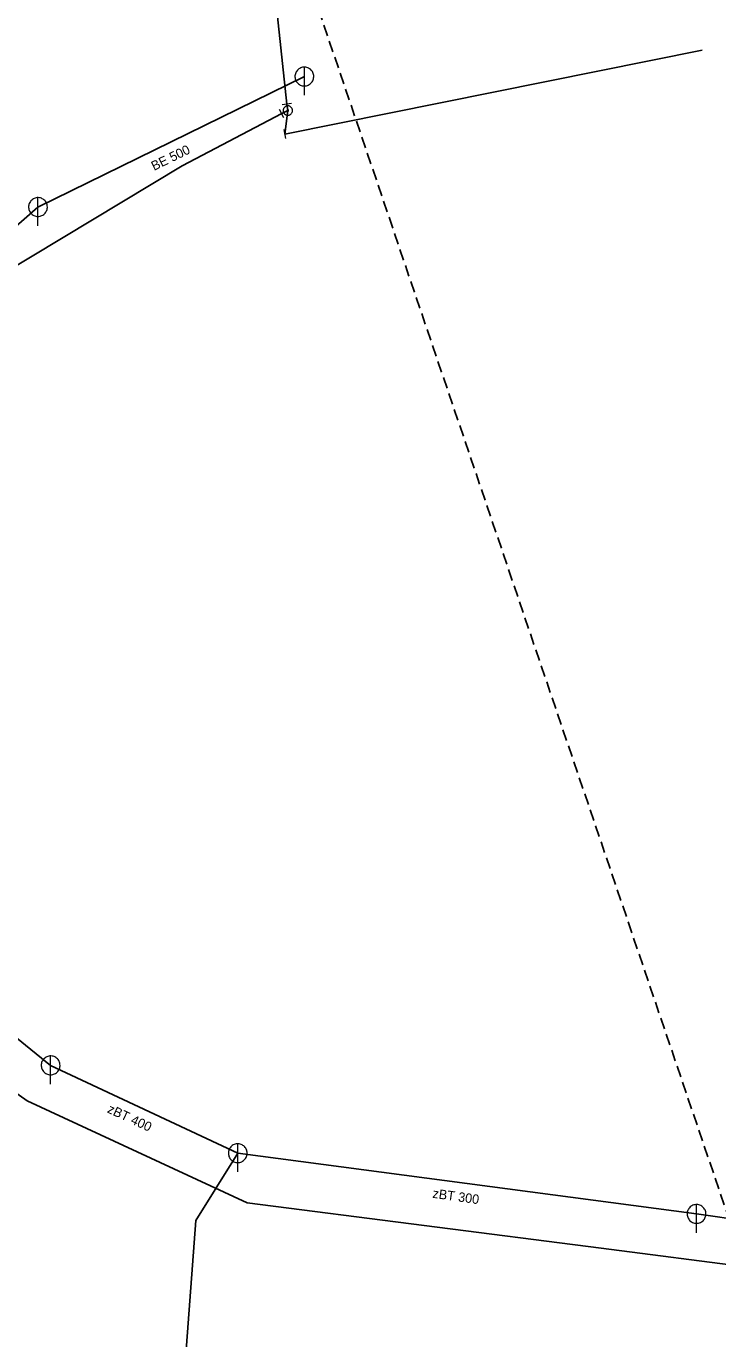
# Model space of a CAD drawing. Extents: x -659250 to -657316, y -997555 to -993684.
# Drawn here: x -658197.6 to -658124, y -995125.1 to -994985.4 of the extents above; entities that cross this region are included whole.
import ezdxf

# ---------------------------------------------------------------- set-up
doc = ezdxf.new("R2010")
doc.units = 0
doc.header["$LTSCALE"] = 0.4
doc.linetypes.add('MEDIUM_DASHED', pattern=[4.5, 3, -1.5])
doc.layers.add('1', color=7, linetype='Continuous')
for name, color, linetype, lineweight in [('14', 7, 'Continuous', 25), ('17', 7, 'Continuous', 25), ('22', 7, 'Continuous', 13), ('34', 7, 'Continuous', 13), ('47', 7, 'Continuous', 13), ('63', 7, 'MEDIUM_DASHED', 25)]:
    doc.layers.add(name, color=color, linetype=linetype, lineweight=lineweight)

msp = doc.modelspace()

# ---------------------------------------------------------------- linework, layer by layer
at = {"layer": '14'}
for p, q in [((-658168, -994990.77), (-658196.329, -995004.66)), ((-658196.329, -995004.66), (-658210.829, -995017.39)), ((-658230.69, -995067.21), (-658194.982, -995096.022)), ((-658194.982, -995096.022), (-658175.079, -995105.37)), ((-658126.289, -995111.84), (-658175.079, -995105.37)), ((-658069.557, -995119.87), (-658126.289, -995111.84))]:
    msp.add_line(p, q, dxfattribs=at)
msp.add_lwpolyline([(-658175.079, -995105.37), (-658179.557, -995112.526), (-658182.53, -995152.469), (-658232.25, -995143.89), (-658272.949, -995138.75)], dxfattribs=at)
at = {"layer": '17'}
for p, q in [((-658170.079, -994996.89), (-658125.679, -994987.972)), ((-658169.756, -994994.391), (-658170.41, -994994.71)), ((-658169.756, -994994.391), (-658170.079, -994996.89)), ((-658169.87, -994993.71), (-658169.756, -994994.391))]:
    msp.add_line(p, q, dxfattribs=at)
for points in [[(-658177.25, -994941.239), (-658174.441, -994950.724), (-658169.87, -994993.71)], [(-658170.41, -994994.71), (-658180.989, -995000.263), (-658235.118, -995032.881), (-658258.852, -995047.041), (-658259.263, -995047.311)], [(-658062.373, -995124.127), (-658085.166, -995121.715), (-658104.599, -995119.601), (-658136.438, -995115.484), (-658174.067, -995110.673), (-658197.491, -995099.798), (-658221.556, -995082.743), (-658257.348, -995050.168), (-658259.263, -995047.311)]]:
    msp.add_lwpolyline(points, dxfattribs=at)
at = {"layer": '22'}
for p, q in [((-658168, -994992.77), (-658167.999, -994989.77)), ((-658196.329, -995006.66), (-658196.328, -995003.66)), ((-658194.982, -995098.022), (-658194.981, -995095.022)), ((-658175.079, -995107.37), (-658175.078, -995104.37)), ((-658126.289, -995113.84), (-658126.288, -995110.84))]:
    msp.add_line(p, q, dxfattribs=at)
for points in [[(-658167, -994990.77), (-658167.005, -994990.661), (-658167.023, -994990.553), (-658167.053, -994990.447), (-658167.093, -994990.346), (-658167.145, -994990.249), (-658167.207, -994990.159), (-658167.279, -994990.076), (-658167.359, -994990.002), (-658167.447, -994989.936), (-658167.541, -994989.881), (-658167.641, -994989.836), (-658167.746, -994989.803), (-658167.853, -994989.781), (-658167.962, -994989.771), (-658168.072, -994989.773), (-658168.18, -994989.787), (-658168.287, -994989.812), (-658168.39, -994989.849), (-658168.488, -994989.898), (-658168.58, -994989.956), (-658168.666, -994990.025), (-658168.743, -994990.102), (-658168.812, -994990.188), (-658168.871, -994990.28), (-658168.919, -994990.378), (-658168.956, -994990.481), (-658168.982, -994990.588), (-658168.996, -994990.696), (-658168.999, -994990.806), (-658168.989, -994990.915), (-658168.968, -994991.022), (-658168.934, -994991.126), (-658168.89, -994991.226), (-658168.835, -994991.321), (-658168.769, -994991.409), (-658168.695, -994991.489), (-658168.612, -994991.561), (-658168.522, -994991.623), (-658168.426, -994991.675), (-658168.324, -994991.716), (-658168.219, -994991.746), (-658168.111, -994991.764), (-658168.001, -994991.77), (-658167.892, -994991.764), (-658167.784, -994991.746), (-658167.679, -994991.717), (-658167.577, -994991.676), (-658167.48, -994991.624), (-658167.39, -994991.562), (-658167.307, -994991.491), (-658167.232, -994991.411), (-658167.167, -994991.323), (-658167.111, -994991.229), (-658167.067, -994991.129), (-658167.033, -994991.025), (-658167.011, -994990.917), (-658167.001, -994990.808)], [(-658195.329, -995004.66), (-658195.334, -995004.551), (-658195.352, -995004.443), (-658195.382, -995004.337), (-658195.422, -995004.236), (-658195.474, -995004.139), (-658195.536, -995004.049), (-658195.608, -995003.966), (-658195.688, -995003.892), (-658195.776, -995003.826), (-658195.87, -995003.771), (-658195.97, -995003.726), (-658196.075, -995003.693), (-658196.182, -995003.671), (-658196.291, -995003.661), (-658196.401, -995003.663), (-658196.509, -995003.677), (-658196.616, -995003.702), (-658196.719, -995003.739), (-658196.817, -995003.788), (-658196.909, -995003.846), (-658196.995, -995003.915), (-658197.072, -995003.992), (-658197.141, -995004.078), (-658197.2, -995004.17), (-658197.248, -995004.268), (-658197.285, -995004.371), (-658197.311, -995004.478), (-658197.325, -995004.586), (-658197.328, -995004.696), (-658197.318, -995004.805), (-658197.297, -995004.912), (-658197.263, -995005.016), (-658197.219, -995005.116), (-658197.164, -995005.211), (-658197.098, -995005.299), (-658197.024, -995005.379), (-658196.941, -995005.451), (-658196.851, -995005.513), (-658196.755, -995005.565), (-658196.653, -995005.606), (-658196.548, -995005.636), (-658196.44, -995005.654), (-658196.33, -995005.66), (-658196.221, -995005.654), (-658196.113, -995005.636), (-658196.008, -995005.607), (-658195.906, -995005.566), (-658195.809, -995005.514), (-658195.719, -995005.452), (-658195.636, -995005.381), (-658195.561, -995005.301), (-658195.496, -995005.213), (-658195.44, -995005.119), (-658195.396, -995005.019), (-658195.362, -995004.915), (-658195.34, -995004.807), (-658195.33, -995004.698)], [(-658193.982, -995096.022), (-658193.987, -995095.913), (-658194.005, -995095.805), (-658194.035, -995095.699), (-658194.075, -995095.598), (-658194.127, -995095.501), (-658194.189, -995095.411), (-658194.261, -995095.328), (-658194.341, -995095.254), (-658194.429, -995095.188), (-658194.523, -995095.133), (-658194.623, -995095.088), (-658194.728, -995095.055), (-658194.835, -995095.033), (-658194.944, -995095.023), (-658195.054, -995095.025), (-658195.162, -995095.039), (-658195.269, -995095.064), (-658195.372, -995095.101), (-658195.47, -995095.15), (-658195.562, -995095.208), (-658195.648, -995095.277), (-658195.725, -995095.354), (-658195.794, -995095.44), (-658195.853, -995095.532), (-658195.901, -995095.63), (-658195.938, -995095.733), (-658195.964, -995095.84), (-658195.978, -995095.948), (-658195.981, -995096.058), (-658195.971, -995096.167), (-658195.95, -995096.274), (-658195.916, -995096.378), (-658195.872, -995096.478), (-658195.817, -995096.573), (-658195.751, -995096.661), (-658195.677, -995096.741), (-658195.594, -995096.813), (-658195.504, -995096.875), (-658195.408, -995096.927), (-658195.306, -995096.968), (-658195.201, -995096.998), (-658195.093, -995097.016), (-658194.983, -995097.022), (-658194.874, -995097.016), (-658194.766, -995096.998), (-658194.661, -995096.969), (-658194.559, -995096.928), (-658194.462, -995096.876), (-658194.372, -995096.814), (-658194.289, -995096.743), (-658194.214, -995096.663), (-658194.149, -995096.575), (-658194.093, -995096.481), (-658194.049, -995096.381), (-658194.015, -995096.277), (-658193.993, -995096.169), (-658193.983, -995096.06)], [(-658174.079, -995105.37), (-658174.084, -995105.261), (-658174.102, -995105.153), (-658174.132, -995105.047), (-658174.172, -995104.946), (-658174.224, -995104.849), (-658174.286, -995104.759), (-658174.358, -995104.676), (-658174.438, -995104.602), (-658174.526, -995104.536), (-658174.62, -995104.481), (-658174.72, -995104.436), (-658174.825, -995104.403), (-658174.932, -995104.381), (-658175.041, -995104.371), (-658175.151, -995104.373), (-658175.259, -995104.387), (-658175.366, -995104.412), (-658175.469, -995104.449), (-658175.567, -995104.498), (-658175.659, -995104.556), (-658175.745, -995104.625), (-658175.822, -995104.702), (-658175.891, -995104.788), (-658175.95, -995104.88), (-658175.998, -995104.978), (-658176.035, -995105.081), (-658176.061, -995105.188), (-658176.075, -995105.296), (-658176.078, -995105.406), (-658176.068, -995105.515), (-658176.047, -995105.622), (-658176.013, -995105.726), (-658175.969, -995105.826), (-658175.914, -995105.921), (-658175.848, -995106.009), (-658175.774, -995106.089), (-658175.691, -995106.161), (-658175.601, -995106.223), (-658175.505, -995106.275), (-658175.403, -995106.316), (-658175.298, -995106.346), (-658175.19, -995106.364), (-658175.08, -995106.37), (-658174.971, -995106.364), (-658174.863, -995106.346), (-658174.758, -995106.317), (-658174.656, -995106.276), (-658174.559, -995106.224), (-658174.469, -995106.162), (-658174.386, -995106.091), (-658174.311, -995106.011), (-658174.246, -995105.923), (-658174.19, -995105.829), (-658174.146, -995105.729), (-658174.112, -995105.625), (-658174.09, -995105.517), (-658174.08, -995105.408)], [(-658125.289, -995111.84), (-658125.294, -995111.731), (-658125.312, -995111.623), (-658125.342, -995111.517), (-658125.382, -995111.416), (-658125.434, -995111.319), (-658125.496, -995111.229), (-658125.568, -995111.146), (-658125.648, -995111.072), (-658125.736, -995111.006), (-658125.83, -995110.951), (-658125.93, -995110.906), (-658126.035, -995110.873), (-658126.142, -995110.851), (-658126.251, -995110.841), (-658126.361, -995110.843), (-658126.469, -995110.857), (-658126.576, -995110.882), (-658126.679, -995110.919), (-658126.777, -995110.968), (-658126.869, -995111.026), (-658126.955, -995111.095), (-658127.032, -995111.172), (-658127.101, -995111.258), (-658127.16, -995111.35), (-658127.208, -995111.448), (-658127.245, -995111.551), (-658127.271, -995111.658), (-658127.285, -995111.766), (-658127.288, -995111.876), (-658127.278, -995111.985), (-658127.257, -995112.092), (-658127.223, -995112.196), (-658127.179, -995112.296), (-658127.124, -995112.391), (-658127.058, -995112.479), (-658126.984, -995112.559), (-658126.901, -995112.631), (-658126.811, -995112.693), (-658126.715, -995112.745), (-658126.613, -995112.786), (-658126.508, -995112.816), (-658126.4, -995112.834), (-658126.29, -995112.84), (-658126.181, -995112.834), (-658126.073, -995112.816), (-658125.968, -995112.787), (-658125.866, -995112.746), (-658125.769, -995112.694), (-658125.679, -995112.632), (-658125.596, -995112.561), (-658125.521, -995112.481), (-658125.456, -995112.393), (-658125.4, -995112.299), (-658125.356, -995112.199), (-658125.322, -995112.095), (-658125.3, -995111.987), (-658125.29, -995111.878)]]:
    msp.add_lwpolyline(points, close=True, dxfattribs=at)
at = {"layer": '34'}
for p, q in [((-658170.177, -994995.152), (-658170.641, -994994.267)), ((-658169.375, -994993.638), (-658170.364, -994993.78)), ((-658170.164, -994996.397), (-658169.994, -994997.382))]:
    msp.add_line(p, q, dxfattribs=at)
at = {"layer": '47'}
for points in [[(-658169.256, -994994.391), (-658169.259, -994994.338), (-658169.267, -994994.286), (-658169.281, -994994.237), (-658169.299, -994994.188), (-658169.323, -994994.141), (-658169.352, -994994.097), (-658169.385, -994994.056), (-658169.422, -994994.019), (-658169.462, -994993.987), (-658169.506, -994993.958), (-658169.553, -994993.933), (-658169.602, -994993.916), (-658169.652, -994993.902), (-658169.704, -994993.894), (-658169.756, -994993.891), (-658169.808, -994993.894), (-658169.86, -994993.902), (-658169.911, -994993.916), (-658169.959, -994993.933), (-658170.006, -994993.958), (-658170.05, -994993.987), (-658170.091, -994994.019), (-658170.128, -994994.056), (-658170.161, -994994.097), (-658170.189, -994994.141), (-658170.213, -994994.188), (-658170.232, -994994.237), (-658170.245, -994994.286), (-658170.253, -994994.338), (-658170.256, -994994.391), (-658170.253, -994994.443), (-658170.245, -994994.495), (-658170.232, -994994.546), (-658170.213, -994994.593), (-658170.189, -994994.641), (-658170.161, -994994.684), (-658170.128, -994994.725), (-658170.091, -994994.762), (-658170.05, -994994.796), (-658170.006, -994994.823), (-658169.959, -994994.848), (-658169.911, -994994.867), (-658169.86, -994994.879), (-658169.808, -994994.887), (-658169.756, -994994.891), (-658169.704, -994994.887), (-658169.652, -994994.879), (-658169.602, -994994.867), (-658169.553, -994994.848), (-658169.506, -994994.823), (-658169.462, -994994.796), (-658169.422, -994994.762), (-658169.385, -994994.725), (-658169.352, -994994.684), (-658169.323, -994994.641), (-658169.299, -994994.593), (-658169.281, -994994.546), (-658169.267, -994994.495), (-658169.259, -994994.443)], [(-658169.674, -994994.391), (-658169.674, -994994.382), (-658169.676, -994994.374), (-658169.678, -994994.365), (-658169.681, -994994.357), (-658169.685, -994994.35), (-658169.69, -994994.343), (-658169.695, -994994.335), (-658169.701, -994994.33), (-658169.708, -994994.325), (-658169.715, -994994.32), (-658169.723, -994994.316), (-658169.731, -994994.313), (-658169.739, -994994.311), (-658169.747, -994994.308), (-658169.756, -994994.308), (-658169.765, -994994.308), (-658169.773, -994994.311), (-658169.781, -994994.313), (-658169.789, -994994.316), (-658169.797, -994994.32), (-658169.804, -994994.325), (-658169.811, -994994.33), (-658169.817, -994994.335), (-658169.823, -994994.343), (-658169.827, -994994.35), (-658169.831, -994994.357), (-658169.834, -994994.365), (-658169.836, -994994.374), (-658169.838, -994994.382), (-658169.838, -994994.391), (-658169.838, -994994.399), (-658169.836, -994994.407), (-658169.834, -994994.416), (-658169.831, -994994.424), (-658169.827, -994994.431), (-658169.823, -994994.438), (-658169.817, -994994.446), (-658169.811, -994994.451), (-658169.804, -994994.458), (-658169.797, -994994.462), (-658169.789, -994994.465), (-658169.781, -994994.468), (-658169.773, -994994.47), (-658169.765, -994994.473), (-658169.756, -994994.473), (-658169.747, -994994.473), (-658169.739, -994994.47), (-658169.731, -994994.468), (-658169.723, -994994.465), (-658169.715, -994994.462), (-658169.708, -994994.458), (-658169.701, -994994.451), (-658169.695, -994994.446), (-658169.69, -994994.438), (-658169.685, -994994.431), (-658169.681, -994994.424), (-658169.678, -994994.416), (-658169.676, -994994.407), (-658169.674, -994994.399)]]:
    msp.add_lwpolyline(points, close=True, dxfattribs=at)
at = {"layer": '63'}
msp.add_lwpolyline([(-659116.685, -993855.266), (-658551.464, -993848.288), (-658551.464, -993848.288), (-657316.352, -997490.822), (-657316.352, -997490.822), (-657839.705, -997490.822), (-657839.705, -997490.822)], close=True, dxfattribs=at)

# ---------------------------------------------------------------- texts
at = {"layer": '1'}
for s, rotation, p in [('BE 500', 26, (-658183.984, -995000.817)), ('zBT 400 ', 335, (-658189.042, -995101.004)), ('zBT 300 ', 352, (-658154.415, -995110.112))]:
    msp.add_text(s, height=1, rotation=rotation, dxfattribs=at).set_placement(p)

doc.saveas('drawing.dxf')
